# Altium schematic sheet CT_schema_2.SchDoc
size 240 x 321 mm
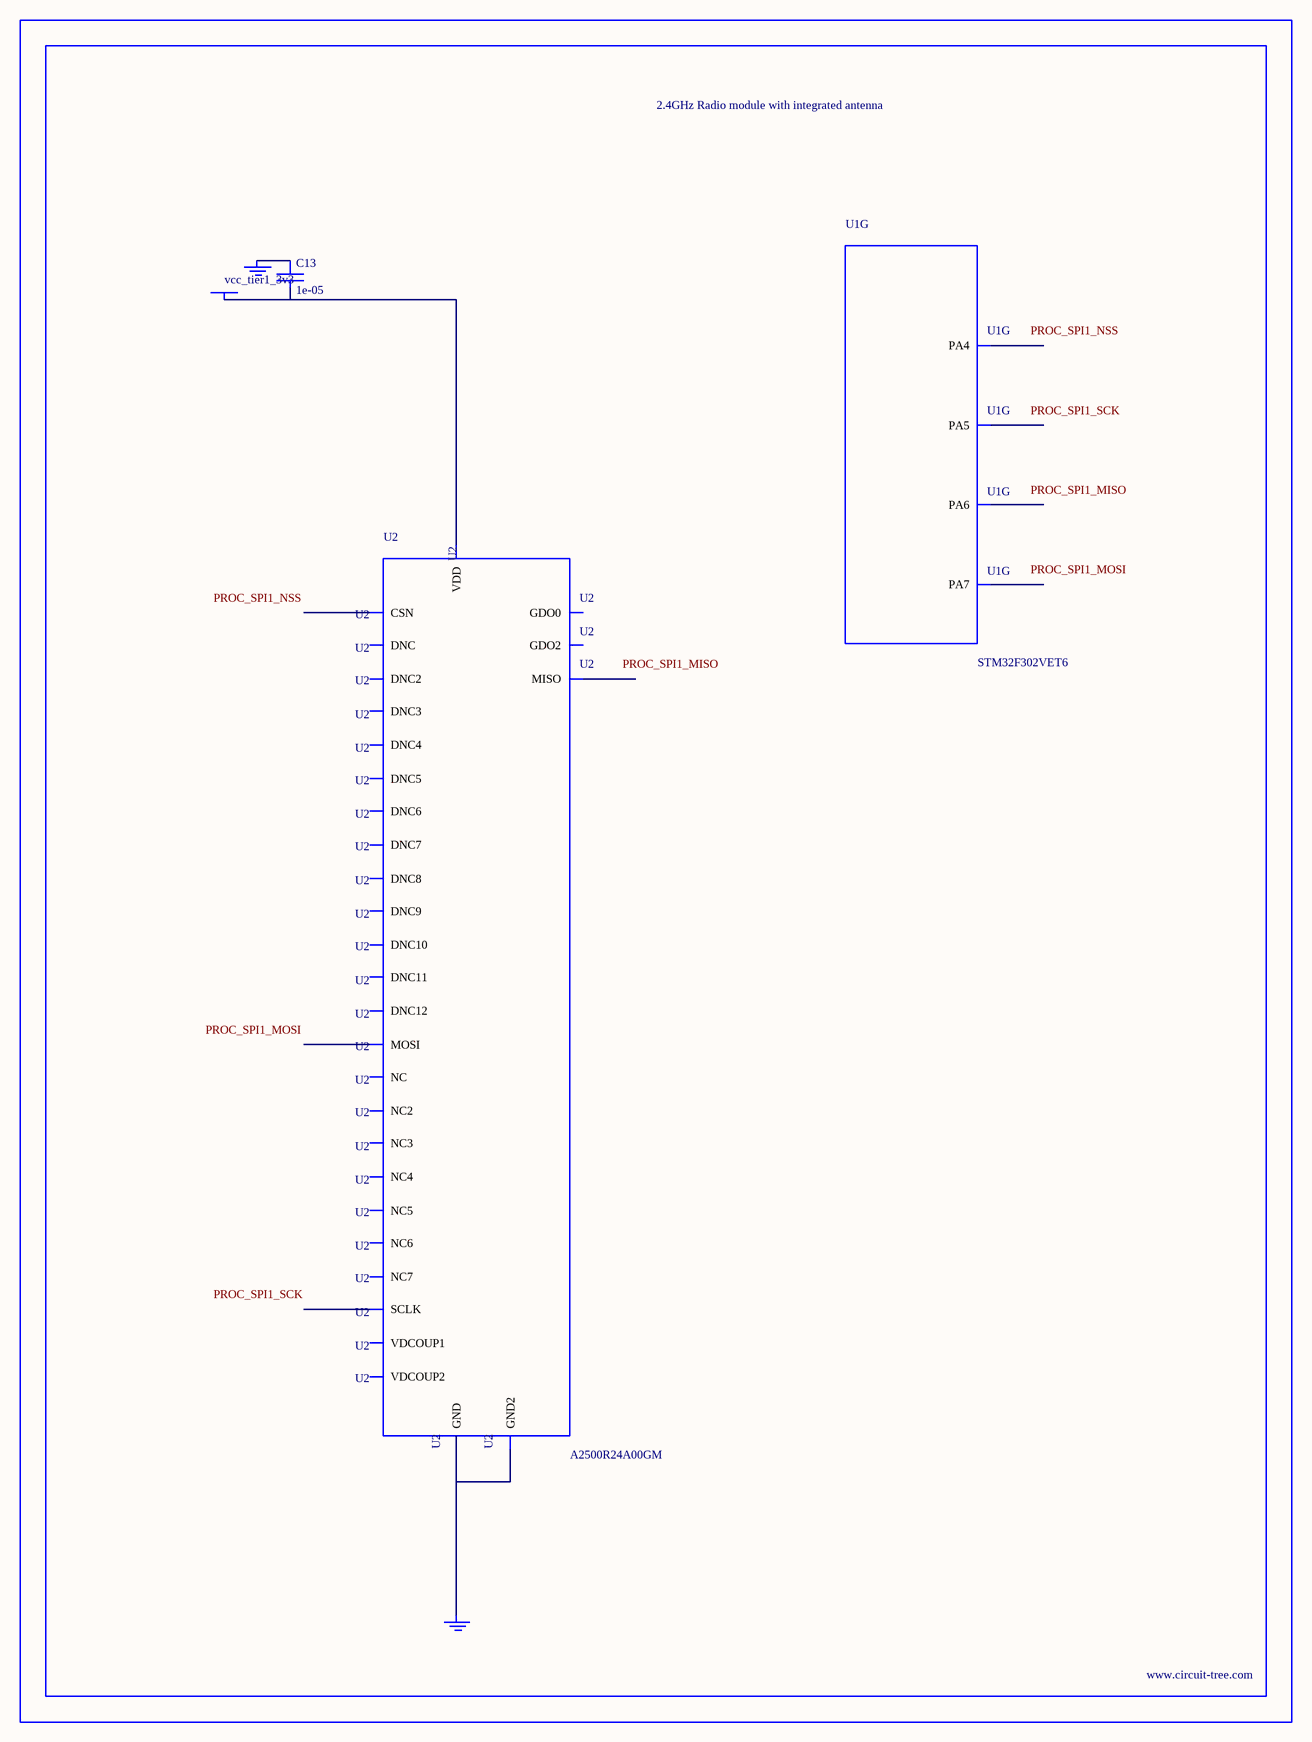
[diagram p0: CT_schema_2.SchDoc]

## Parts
BORDER1  (no value)
C13  1e-05  [C0805]
GND_INSTANCE_1_0  (no value)
GND_INSTANCE_1_1  (no value)
POWER_INSTANCE_1_0  vcc_tier1_3v3
U1  STM32F302VET6  [LQFP100]  (part G of 8)
U2  A2500R24A00GM  [A2500R24A00GM]

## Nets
NetC13_1: C13.1 GND_INSTANCE_1_0.0(GND)
NetC13_2: C13.2 POWER_INSTANCE_1_0.0(PWR) U2.18(VDD)
NetGND_INSTANCE_1_1_0: GND_INSTANCE_1_1.0(GND) U2.8(GND) U2.17(GND2)

Not connected (* = marked no-connect by the designer): U1 29(PA4) 30(PA5) 31(PA6) 32(PA7); U2 1(DNC) 2(DNC2) 3(DNC3) 4(NC) 5(NC2) 6(NC3) 7(VDCOUP1) 9(SCLK) 10(MISO) 11(MOSI) 12(CSN) 13(GDO0) 14(GDO2) 15(VDCOUP2) 16(NC4) 19(NC5) 20(NC6) 21(NC7) 22(DNC4) 23(DNC5) 24(DNC6) 25(DNC7) 26(DNC8) 27(DNC9) 28(DNC10) 29(DNC11) 30(DNC12)

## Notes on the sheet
- Labels drawn without touching a wire or pin: PROC_SPI1_MISO, PROC_SPI1_MOSI, PROC_SPI1_NSS, PROC_SPI1_SCK

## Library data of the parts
BORDER1 = BORDER_PAGE1
C13 = C0805C106K8RACTU
GND_INSTANCE_1_0 GND_INSTANCE_1_1 = GND
POWER_INSTANCE_1_0 = PWR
